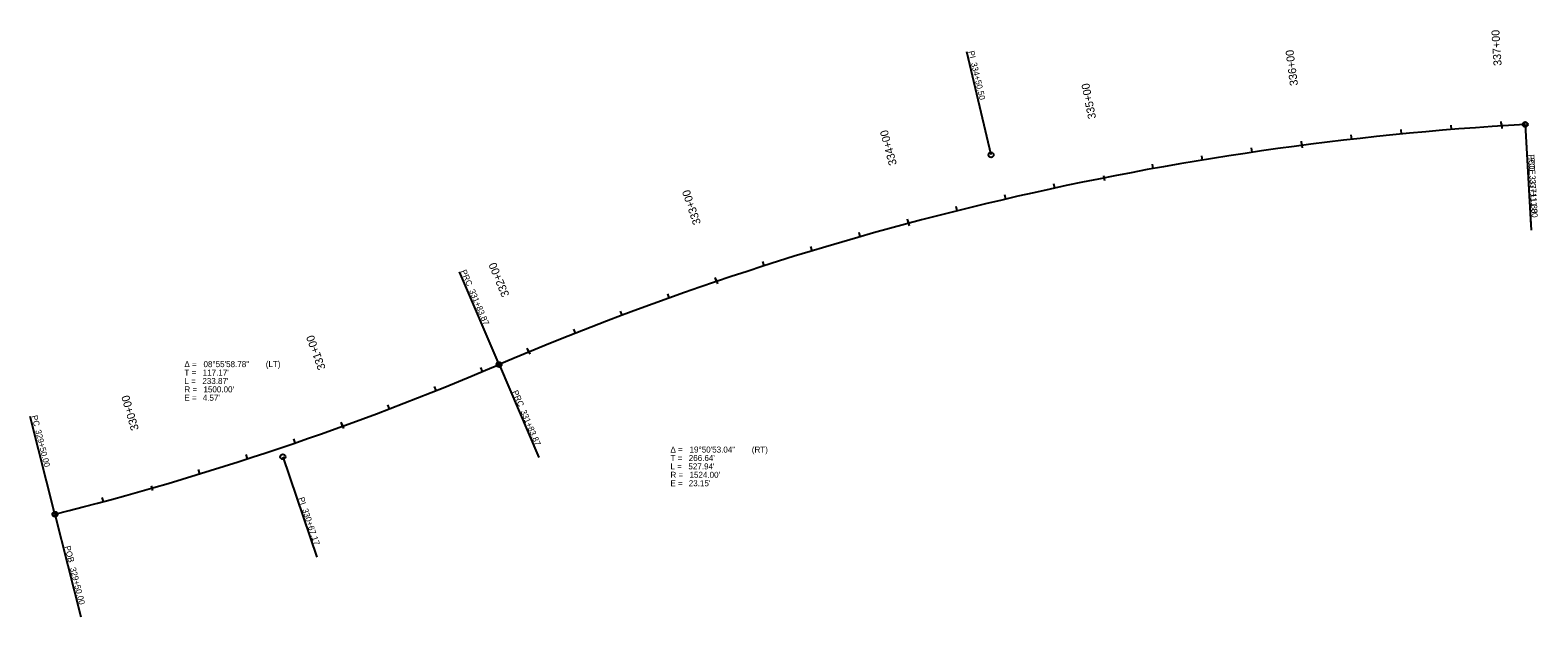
# Model space of a CAD drawing. Extents: x 21448228 to 21448979, y 8416810 to 8417103.
import ezdxf

# ---------------------------------------------------------------- set-up
doc = ezdxf.new("R2010")
doc.units = 0
for name, color, linetype in [('_CIVIL_CONSTRUCTION', 7, 'Continuous'), ('Terrain', 7, 'Continuous'), ('TextAlignment', 7, 'Continuous'), ('TextAlignmentLrg', 7, 'Continuous'), ('TextAlignmentSml', 7, 'Continuous')]:
    doc.layers.add(name, color=color, linetype=linetype)

msp = doc.modelspace()

# ---------------------------------------------------------------- linework, layer by layer
at = {"layer": '_CIVIL_CONSTRUCTION'}
for centre, radius, start, end in [((21449059.39, 8415534.31), 1524, 93.26062, 113.10869), ((21447872.54, 8418315.67), 1500, 284.17569, 293.10869)]:
    msp.add_arc(centre, radius, start, end, dxfattribs=at)
at = {"layer": 'Terrain'}
msp.add_arc((21449059.39, 8415534.31), 1524, 93.26062, 113.10869, dxfattribs=at)
at = {"layer": 'TextAlignment'}
for p, q in [((21448706.5, 8417040.67), (21448694.46, 8417092.08)), ((21448694.46, 8417092.08), (21448694.46, 8417092.08)), ((21448972.71, 8417055.84), (21448975.58, 8417005.52)), ((21448972.71, 8417055.84), (21448975.71, 8417003.13)), ((21448975.58, 8417005.52), (21448975.58, 8417005.52)), ((21448975.71, 8417003.13), (21448975.71, 8417003.13)), ((21448461.26, 8416936.02), (21448441.48, 8416982.38)), ((21448441.48, 8416982.38), (21448441.48, 8416982.38)), ((21448461.26, 8416936.02), (21448481.04, 8416889.67)), ((21448239.89, 8416861.34), (21448227.54, 8416910.21)), ((21448227.54, 8416910.21), (21448227.54, 8416910.21)), ((21448353.49, 8416890.04), (21448370.37, 8416840.01)), ((21448481.04, 8416889.67), (21448481.04, 8416889.67)), ((21448239.89, 8416861.34), (21448252.82, 8416810.15)), ((21448370.37, 8416840.01), (21448370.37, 8416840.01)), ((21448252.82, 8416810.15), (21448252.82, 8416810.15))]:
    msp.add_line(p, q, dxfattribs=at)
for centre, radius in [((21448972.71, 8417055.84), 1.25), ((21448972.71, 8417055.84), 1.07), ((21448706.5, 8417040.67), 1.25), ((21448461.26, 8416936.02), 1.25), ((21448461.26, 8416936.02), 1.25), ((21448353.49, 8416890.04), 1.25), ((21448239.89, 8416861.34), 1.25), ((21448239.89, 8416861.34), 1.07)]:
    msp.add_circle(centre, radius, dxfattribs=at)
at = {"layer": 'TextAlignmentLrg'}
for p, q in [((21448960.93, 8417055.12), (21448960.79, 8417057.3)), ((21448861.42, 8417045.39), (21448861.14, 8417047.56)), ((21448762.53, 8417030.36), (21448763.01, 8417027.96)), ((21448665.39, 8417006.5), (21448664.82, 8417008.61)), ((21448569.71, 8416977.49), (21448569, 8416979.56)), ((21448476.13, 8416942.28), (21448475.29, 8416944.3)), ((21448383.24, 8416905.28), (21448382.5, 8416907.34)), ((21448287.81, 8416875.57), (21448288.49, 8416873.22))]:
    msp.add_line(p, q, dxfattribs=at)
at = {"layer": 'TextAlignmentSml'}
for p, q in [((21448936, 8417053.3), (21448935.82, 8417055.48)), ((21448960.85, 8417056.35), (21448961.01, 8417053.9)), ((21448861.26, 8417046.61), (21448861.58, 8417044.18)), ((21448886.24, 8417048.44), (21448885.99, 8417050.61)), ((21448911.1, 8417051.08), (21448910.89, 8417053.25)), ((21448811.96, 8417038.09), (21448811.61, 8417040.24)), ((21448836.66, 8417041.94), (21448836.34, 8417044.1)), ((21448787.33, 8417033.83), (21448786.94, 8417035.98)), ((21448738.29, 8417024.1), (21448737.83, 8417026.23)), ((21448762.53, 8417030.36), (21448763.01, 8417027.96)), ((21448713.89, 8417018.63), (21448713.4, 8417020.76)), ((21448689.59, 8417012.76), (21448689.06, 8417014.88)), ((21448641.29, 8416999.83), (21448640.69, 8417001.94)), ((21448665.07, 8417007.68), (21448665.71, 8417005.31)), ((21448617.31, 8416992.78), (21448616.68, 8416994.87)), ((21448593.45, 8416985.33), (21448592.78, 8416987.41)), ((21448569.31, 8416978.65), (21448570.1, 8416976.33)), ((21448546.1, 8416969.27), (21448545.36, 8416971.32)), ((21448522.63, 8416960.65), (21448521.86, 8416962.7)), ((21448499.3, 8416951.66), (21448498.5, 8416953.69)), ((21448475.66, 8416943.41), (21448476.6, 8416941.15)), ((21448453.09, 8416932.57), (21448452.25, 8416934.58)), ((21448429.96, 8416923.09), (21448429.15, 8416925.11)), ((21448406.68, 8416913.99), (21448405.9, 8416916.03)), ((21448382.82, 8416906.43), (21448383.66, 8416904.13)), ((21448359.67, 8416896.97), (21448358.96, 8416899.03)), ((21448335.95, 8416889.05), (21448335.28, 8416891.12)), ((21448312.11, 8416881.52), (21448311.47, 8416883.61)), ((21448287.81, 8416875.57), (21448288.49, 8416873.22)), ((21448264.07, 8416867.67), (21448263.5, 8416869.78)), ((21448239.89, 8416861.34), (21448239.35, 8416863.46))]:
    msp.add_line(p, q, dxfattribs=at)

# ---------------------------------------------------------------- texts
at = {"layer": 'TextAlignment'}
for s, rotation, p in [('PI ', 283.18465, (21448695.1, 8417092.23)), ('334+50.50', 283.18465, (21448696.46, 8417086.41)), ('PCC', 273.26062, (21448974.22, 8417040.86)), ('POE ', 273.26062, (21448974.32, 8417039.11)), ('337+11.80', 273.26062, (21448974.82, 8417030.39)), ('337+11.80', 273.26062, (21448974.93, 8417028.36)), ('PRC', 293.10869, (21448442.08, 8416982.64)), ('331+83.87', 293.10869, (21448446.26, 8416972.85)), ('T = ', 359.99859, (21448304.43, 8416930.56)), ('Δ = ', 359.99859, (21448304.43, 8416934.76)), ("117.17'", 359.99859, (21448313.56, 8416930.56)), ('08°55\'58.78"', 359.99859, (21448313.93, 8416934.76)), (' (LT)', 359.99859, (21448343.87, 8416934.76)), ('L = ', 359.99859, (21448304.43, 8416926.36)), ("233.87'", 359.99859, (21448313.37, 8416926.36)), ('R = ', 359.99859, (21448304.43, 8416922.16)), ('E = ', 359.99859, (21448304.43, 8416917.96)), ("4.57'", 359.99859, (21448313.56, 8416917.96)), ("1500.00'", 359.99859, (21448313.92, 8416922.16)), ('PRC', 293.10869, (21448467.76, 8416922.46)), ('PC', 284.17569, (21448228.18, 8416910.37)), ('331+83.87', 293.10869, (21448471.94, 8416912.68)), ('329+50.00', 284.17569, (21448230.01, 8416903.13)), ('T = ', 359.96341, (21448546.69, 8416887.94)), ('Δ = ', 359.96341, (21448546.69, 8416892.14)), ("266.64'", 359.96341, (21448555.81, 8416887.94)), ('19°50\'53.04"', 359.96341, (21448556.19, 8416892.14)), (' (RT)', 359.96341, (21448586.13, 8416892.12)), ('L = ', 359.96341, (21448546.69, 8416883.74)), ('R = ', 359.96341, (21448546.69, 8416879.54)), ("527.94'", 359.96341, (21448555.63, 8416883.74)), ("1524.00'", 359.96341, (21448556.17, 8416879.54)), ('E = ', 359.96341, (21448546.68, 8416875.34)), ("23.15'", 359.96341, (21448555.81, 8416875.34)), ('PI ', 288.64219, (21448361.17, 8416869.32)), ('330+67.17', 288.64219, (21448363.08, 8416863.66)), ('POB ', 284.17569, (21448244.64, 8416845.22)), ('329+50.00', 284.17569, (21448247.35, 8416834.47))]:
    msp.add_text(s, height=3, rotation=rotation, dxfattribs=at).set_placement(p)
at = {"layer": 'TextAlignmentLrg'}
for s, rotation, p in [('335+00', 101.22339, (21448758.89, 8417058.98)), ('330+00', 106.08555, (21448281.76, 8416903.78))]:
    msp.add_text(s, height=4.008, rotation=rotation, dxfattribs=at).set_placement(p)
at = {"layer": 'TextAlignmentSml'}
for s, rotation, p in [('337+00', 93.70426, (21448960.99, 8417085.19)), ('336+00', 97.46383, (21448859.51, 8417075.4)), ('335+00', 101.22339, (21448758.89, 8417058.98)), ('334+00', 104.98296, (21448659.57, 8417035.99)), ('333+00', 108.74253, (21448561.96, 8417006.55)), ('332+00', 112.50209, (21448466.5, 8416970.76)), ('331+00', 109.90527, (21448374.91, 8416934.17)), ('330+00', 106.08555, (21448281.76, 8416903.78))]:
    msp.add_text(s, height=4.008, rotation=rotation, dxfattribs=at).set_placement(p)

doc.saveas('drawing.dxf')
